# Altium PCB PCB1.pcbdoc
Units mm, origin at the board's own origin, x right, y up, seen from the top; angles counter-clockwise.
Board outline 92.1 x 134 mm, 2 copper layers (Top Layer, Bottom Layer); 90 components, 71 nets, 345 pads, 182 vias.
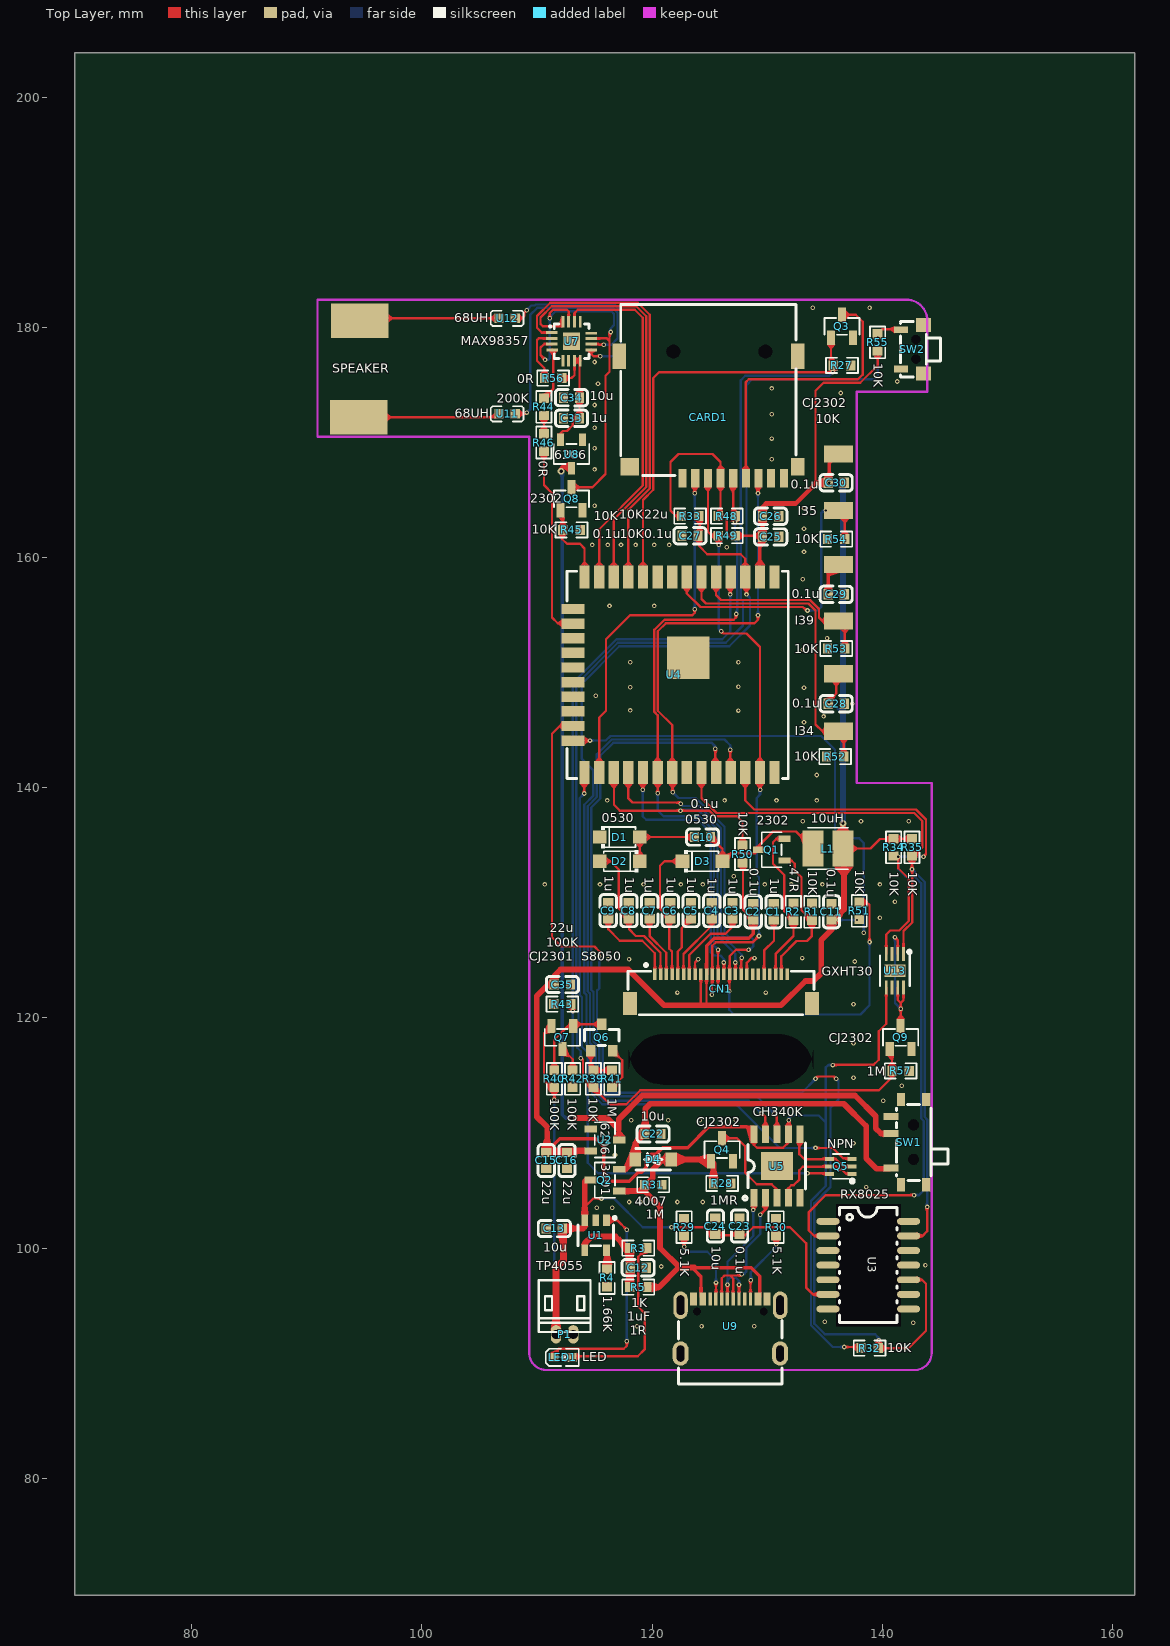
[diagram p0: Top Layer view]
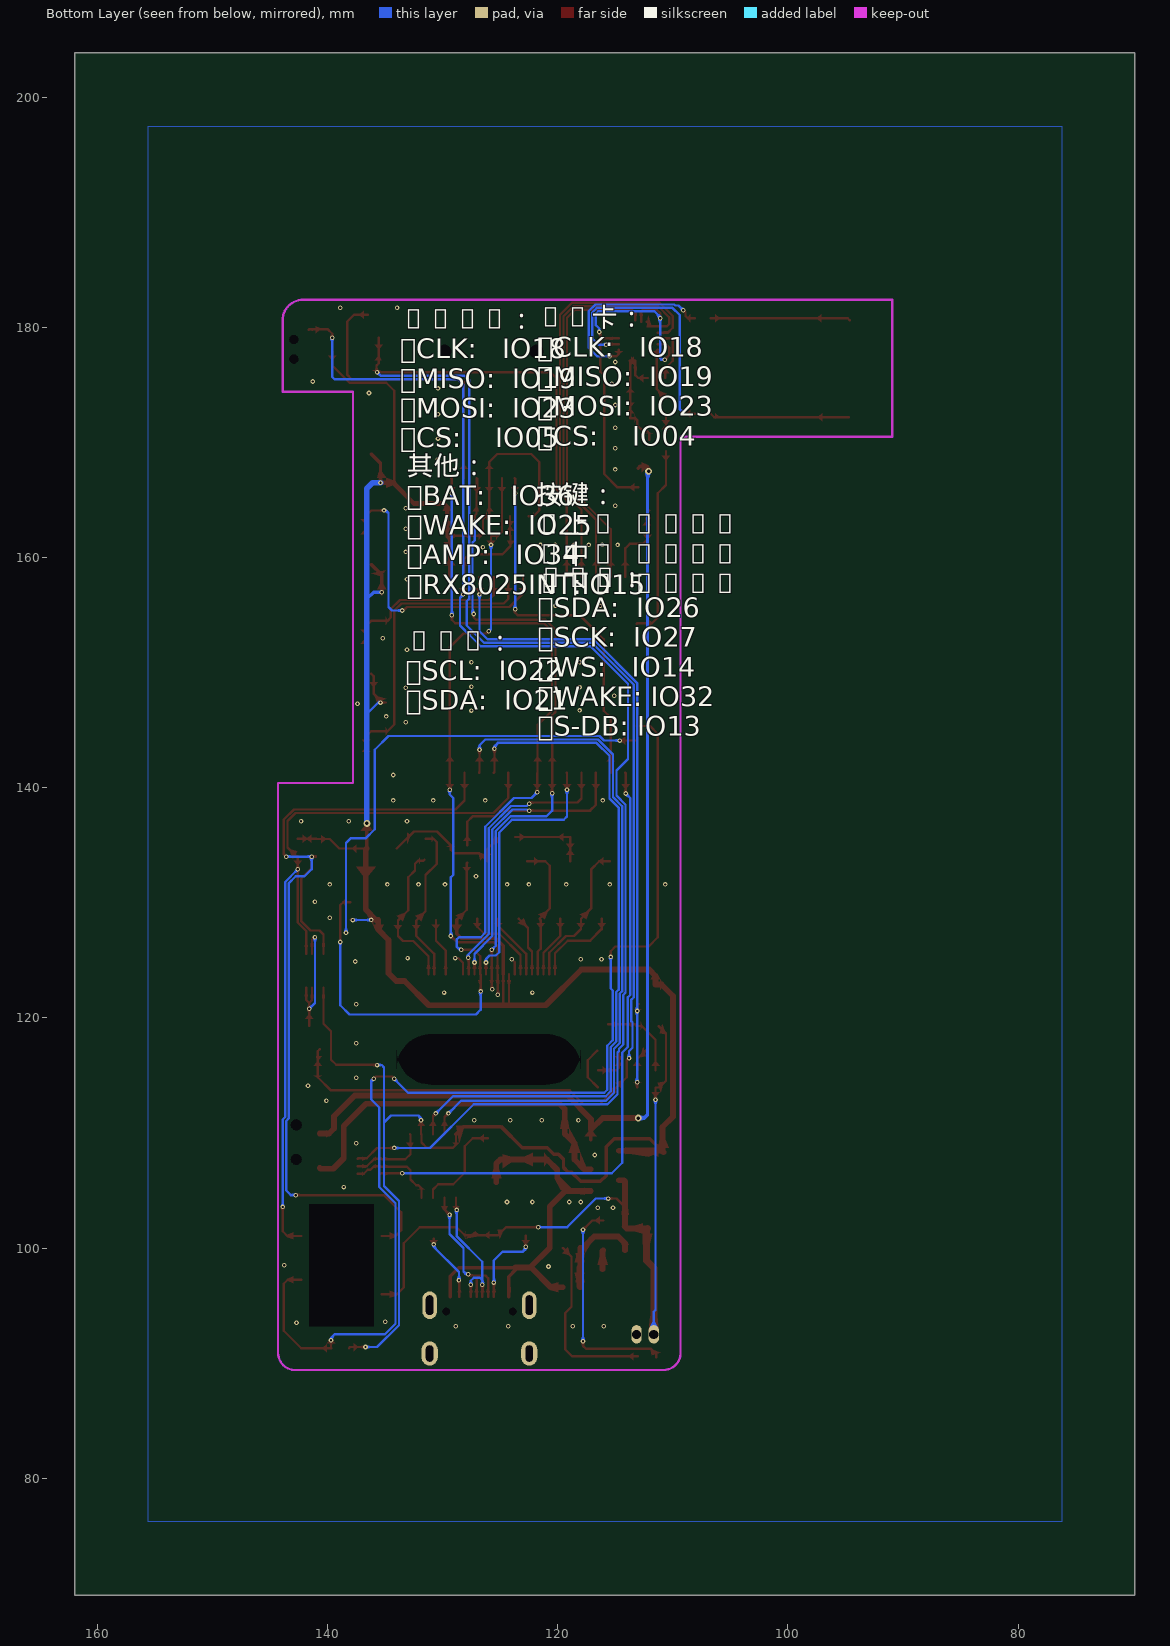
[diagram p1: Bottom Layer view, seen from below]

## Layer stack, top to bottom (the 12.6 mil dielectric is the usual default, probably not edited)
Top Layer: signal copper (thickness not stored)
Dielectric: dielectric 0.32, FR-4, Dk 4.8
Bottom Layer: signal copper (thickness not stored)

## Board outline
161.95,69.85 69.85,69.85 69.85,203.85 161.95,203.85
cut-out: 120.986,118.6 130.986,118.6 cw(c130.986,115.6) 133.986,115.6 133.986,117.2 cw(c130.986,117.2) 130.986,114.2 120.986,114.2 cw(c120.986,117.2) 117.986,117.2 117.986,115.6 cw(c120.986,115.6)
cut-out: 136,103.8 141.6,103.8 141.6,93.2 136,93.2

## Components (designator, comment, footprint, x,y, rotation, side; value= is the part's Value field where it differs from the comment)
C1 "CAP_0603" C0603 130.586,129.214 r270 top
C2 "CAP_0603" C0603 128.786,129.214 r270 top
C3 "CAP_0603" C0603 126.986,129.314 r270 top
C4 "CAP_0603" C0603 125.186,129.314 r270 top
C5 "CAP_0603" C0603 123.386,129.314 r270 top
C6 "CAP_0603" C0603 121.586,129.314 r270 top
C7 "CAP_0603" C0603 119.786,129.314 r270 top
C8 "CAP_0603" C0603 117.986,129.314 r270 top
C9 "CAP_0603" C0603 116.186,129.314 r270 top
C10 "CAP_0603" C0603 124.386,135.714 r180 top
C11 "CAP_0603" C0603 135.586,129.214 r270 top
C12 "CAP_0603" C0603 118.8,98.3 r0 top
C13 "CAP_0603" C0603 111.5,101.7 r180 top
C15 "CAP_0603" C0603 110.805,107.616 r90 top
C16 "CAP_0603" C0603 112.605,107.616 r90 top
C22 "CAP_0603" C0603 120.086,109.914 r180 top
C23 "CAP_0603" C0603 127.6,101.9 r270 top
C24 "CAP_0603" C0603 125.5,101.9 r270 top
C25 "CAP_0603" C0603 130.3,161.8 r180 top
C26 "CAP_0603" C0603 130.3,163.6 r180 top
C27 "CAP_0603" C0603 123.3,161.9 r0 top
C28 "CAP_0603" C0603 136,147.3 r0 top
C29 "CAP_0603" C0603 136,156.8 r0 top
C30 "CAP_0603" C0603 136,166.5 r0 top
C33 "CAP_0603" C0603 113,172.1 r0 top
C34 "CAP_0603" C0603 113,173.9 r0 top
C35 "CAP_0603" C0603 112.2,122.9 r180 top
CARD1 "XKTF-015-G" TF-SMD_XKTF-015-N 124.9,172.2 r180 top
CN1 "HW05150-240R00" FPC-SMD_24P-P0.50_HW05150-240R00 125.986,122.514 r0 top
D1 "MBR0530" SOD-123FL_L2.7-W1.8-LS3.7-RD 117.186,135.714 r0 top
D2 "MBR0530" SOD-123FL_L2.7-W1.8-LS3.7-RD 117.186,133.614 r180 top
D3 "MBR0530" SOD-123FL_L2.7-W1.8-LS3.7-RD 124.386,133.614 r0 top
D4 "SM4007PL_C64898" SOD-123F_L2.8-W1.8-LS3.7-RD 120.1,107.7 r0 top
L1 "SCCD32-100KT" IND-SMD_L3.5-W3.0 135.286,134.714 r0 top
LED1 "LED_0603-B" LED_0603 112.3,90.5 r0 top
P1 "弯针1.25*2" CON1.5*2-90 112.4,92.5 r180 top
Q1 "SL2302" SOT-23-3_L3.0-W1.7-P0.95-LS2.9-BR 130.386,134.614 r0 top
Q2 "CJ3401" SOT-23-3_L2.9-W1.6-P1.90-LS2.8-BR 115.9,105.9 r0 top
Q3 "CJ2302" SOT-23-3_L2.9-W1.3-P1.90-LS2.4-BR 136.5,180.1 r270 top
Q4 "CJ2302" SOT-23-3_L2.9-W1.3-P1.90-LS2.4-BR 126.085,108.547 r270 top
Q5 "PUMH9,115" SOT-363_L2.0-W1.3-P0.65-LS2.1-BL 136.4,107.1 r90 top
Q6 "S8050_SOT_NPN" S8050_SOT-23 115.5,118.3 r270 top
Q7 "CJ2301" SOT-23-3_L2.9-W1.3-P1.90-LS2.4-BR 112.2,118.3 r90 top
Q8 "CJ2302" SOT-23-3_L2.9-W1.3-P1.90-LS2.4-BR 113,165.1 r270 top
Q9 "CJ2302" SOT-23-3_L2.9-W1.3-P1.90-LS2.4-BR 141.6,118.3 r270 top
R1 "Res_0603" R0603 133.886,129.214 r270 top
R2 "Res_0603" R0603 132.286,129.214 r270 top
R3 "Res_0603" R0603 118.8,100 r0 top
R4 "Res_0603" R0603 116.1,97.4 r270 top
R5 "Res_0603" R0603 118.8,96.6 r180 top
R27 "Res_0603" R0603 136.5,176.7 r0 top
R28 "Res_0603" R0603 126.086,105.614 r180 top
R29 "Res_0603" R0603 122.786,101.814 r270 top
R30 "Res_0603" R0603 130.786,101.814 r90 top
R31 "Res_0603" R0603 120.1,105.5 r180 top
R32 "Res_0603" R0603 138.9,91.3 r180 top
R33 "Res_0603" R0603 123.3,163.6 r0 top
R34 "Res_0603" R0603 140.986,134.814 r270 top
R35 "Res_0603" R0603 142.586,134.814 r270 top
R39 "Res_0603" R0603 114.9,114.7 r90 top
R40 "Res_0603" R0603 111.5,114.7 r90 top
R41 "Res_0603" R0603 116.5,114.7 r270 top
R42 "Res_0603" R0603 113.1,114.7 r270 top
R43 "Res_0603" R0603 112.2,121.2 r180 top
R44 "Res_0603" R0603 110.6,173.1 r90 top
R45 "Res_0603" R0603 113,162.4 r180 top
R46 "Res_0603" R0603 110.6,170 r270 top
R48 "Res_0603" R0603 126.5,163.6 r0 top
R49 "Res_0603" R0603 126.5,161.9 r180 top
R50 "Res_0603" R0603 127.859,134.24 r90 top
R51 "Res_0603" R0603 138,129.3 r90 top
R52 "Res_0603" R0603 135.9,142.7 r180 top
R53 "Res_0603" R0603 136,152.1 r180 top
R54 "Res_0603" R0603 136,161.6 r180 top
R55 "Res_0603" R0603 139.6,178.7 r90 top
R56 "Res_0603" R0603 111.4,175.6 r180 top
R57 "Res_0603" R0603 141.6,115.4 r0 top
SW1 "MSK12CO2-BDM" SW-SMD_MSK12CO2-BDM 142.3,109.2 r90 top
SW2 "TS-1010-C-A" KEY-SMD_TX-1010-X-X 142.6,178.1 r270 top
U1 "TP4055" SOT-23-5_L3.0-W1.7-P0.95-LS2.8-BR 115.1,101.1 r90 top
U2 "ME6206A33M3G" SOT-23-3_L2.9-W1.6-P1.90-LS2.8-BR 115.9,109.4 r180 top
U3 "RX8025T-UB" SOIC-14_L10.1-W5.0-P1.27-LS7.4-BL 138.786,98.514 r270 top
U4 "ESP32-WROOM-32UE-N4_C2934568" WIFI-SMD_ESP32-WROOM-32UE-A 121.886,149.814 r270 top
U5 "CH340K" ESOP-10_L4.9-W3.9-P1.00-LS6.2-BL-EP 130.843,107.131 r0 top
U7 "MAX98357AETE+T" TQFN-16_L3.0-W3.0-P0.50-BL-EP1.5 113,178.8 r270 top
U8 "ME6206A33M3G" SOT-23-3_L2.9-W1.6-P1.90-LS2.8-BR 113,169 r90 top
U9 "TYPE-C16PIN母座 板上四脚三次molding" USB-SMD_TYPE-C16PIN 126.8,93.2 r0 top
U11 "EBLS1608-3R9K" L0603 107.4,172.5 r180 top
U12 "EBLS1608-3R9K" L0603 107.4,180.8 r180 top
U13 "GXHT30" DFN-8_L2.5-W2.5-P0.50-BL-EP 141.1,124.1 r180 top

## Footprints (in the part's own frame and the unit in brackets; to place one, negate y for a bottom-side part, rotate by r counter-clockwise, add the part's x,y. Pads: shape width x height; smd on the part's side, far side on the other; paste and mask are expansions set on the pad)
C0603 [mm]
  rect 0.8x0.9 smd paste+0 mask+0.051: 1(-0.7,0) 2(0.7,0)
  silkscreen extent -1.41,-0.71 1.39,0.72
CON1.5*2-90 [mm]
  oval 0.9x1.6 hole 0.8 paste+0 mask+0.102: 1(-0.75,0) 2(0.75,0)
  silkscreen extent -2.25,-4.7 2.25,-0.2
DFN-8_L2.5-W2.5-P0.50-BL-EP [mm]
  rect 0.25x1.25 smd paste+0 mask+0.051: 1(-0.75,-1.454) 2(-0.25,-1.454) 3(0.25,-1.454) 4(0.75,-1.454) 5(0.75,1.454) 6(0.25,1.454) 7(-0.25,1.454) 8(-0.75,1.454)
  rect 1.8x1.1 smd paste+0 mask+0.051: 9(0,0)
  silkscreen extent -1.39,-1.77 1.3,1.3
ESOP-10_L4.9-W3.9-P1.00-LS6.2-BL-EP [mm]
  rect 0.6x1.5 smd paste+0 mask+0.051: 1(-2,-2.75) 2(-1,-2.75) 3(0,-2.75) 4(1,-2.75) 5(2,-2.75) 6(2,2.75) 7(1,2.75) 8(0,2.75) 9(-1,2.75) 10(-2,2.75)
  rect 2.8x2.4 smd paste+0 mask+0.051: 11(0,0)
  silkscreen extent -2.94,-2.96 2.5,2
FPC-SMD_24P-P0.50_HW05150-240R00 [mm]
  rect 0.3x1 smd paste+0 mask+0.05: 1(-5.75,1.275) 2(-5.25,1.275) 3(-4.75,1.275) 4(-4.25,1.275) 5(-3.75,1.275) 6(-3.25,1.275) 7(-2.75,1.275) 8(-2.25,1.275) 9(-1.75,1.275) 10(-1.25,1.275) 11(-0.75,1.275) 12(-0.25,1.275) 13(0.25,1.275) 14(0.75,1.275) 15(1.25,1.275) 16(1.75,1.275) 17(2.25,1.275) 18(2.752,1.275) 19(3.25,1.275) 20(3.75,1.275) 21(4.25,1.275) 22(4.75,1.275) 23(5.25,1.275) 24(5.75,1.275)
  rect 1.2x2 smd paste+0 mask+0.05: 25(7.9,-1.275) 26(-7.9,-1.275)
  silkscreen extent -8.09,-2.24 8.07,2.21
IND-SMD_L3.5-W3.0 [mm]
  rect 1.8x3.12 smd paste+0 mask+0.051: 1(1.303,0) 2(-1.303,0)
  silkscreen extent -1.75,-1.8 1.75,1.8
KEY-SMD_TX-1010-X-X [mm]
  rect 0.6x1.2 smd paste+0 mask+0.051: 1(-1.7,-0.975) 2(1.7,-0.975)
  rect 1.2x1.3 smd paste+0 mask+0.051: 3(-2.1,0.975) 4(2.1,0.975)
  Multi-Layer board cut-out: -0.85,0.725 -1.023,0.685 -1.163,0.574 -1.24,0.414 -1.24,0.236 -1.163,0.076 -1.023,-0.035 -0.85,-0.075 -0.85,-0.075 -0.676,-0.035 -0.537,0.076 -0.46,0.236 -0.46,0.414 -0.537,0.574 -0.676,0.685 -0.85,0.725
  Multi-Layer board cut-out: 0.85,0.725 0.677,0.685 0.537,0.574 0.46,0.414 0.46,0.236 0.537,0.076 0.677,-0.035 0.85,-0.075 0.85,-0.075 1.024,-0.035 1.163,0.076 1.24,0.236 1.24,0.414 1.163,0.574 1.024,0.685 0.85,0.725
  silkscreen extent -2.4,-1.03 2.4,2.48
L0603 [mm]
  rect 0.8x0.864 smd paste-100 mask+0.051: 1(-0.7,0) 2(0.7,0)
  silkscreen extent -1.42,-0.65 1.41,0.67
LED_0603 [mil]
  rect 31.5x31.5 smd paste+0 mask+2: 1(-33.5,-0.4) 2(29.5,-0.2)
  silkscreen extent -61,-30 53,30
R0603 [mm]
  rect 0.806x0.864 smd paste-100 mask+0.051: 1(-0.753,0) 2(0.753,0)
  silkscreen extent -1.39,-0.66 1.39,0.66
S8050_SOT-23 [mm]
  rect 1x0.8 smd paste+0 mask+0.051: 1(1.15,-0.823) 2(1.15,1.077) 3(-1.15,0.127)
  silkscreen extent -0.7,-1.37 0.7,1.63
SOD-123F_L2.8-W1.8-LS3.7-RD [mm]
  rect 1x1.2 smd paste+0 mask+0.051: 1(-1.55,0) 2(1.55,0)
  silkscreen extent -1.52,-0.93 1.49,0.95
SOD-123FL_L2.7-W1.8-LS3.7-RD [mm]
  rect 1.2x1.15 smd paste+0 mask+0.051: 1(-1.735,0) 2(1.735,0)
  silkscreen extent -1.6,-0.95 1.38,0.95
SOIC-14_L10.1-W5.0-P1.27-LS7.4-BL [mm]
  oval 0.6x2 smd paste+0 mask+0.051: 1(-3.81,-3.5) 2(-2.54,-3.5) 3(-1.27,-3.5) 4(0,-3.5) 5(1.27,-3.5) 6(2.54,-3.5) 7(3.81,-3.5) 8(3.81,3.5) 9(2.54,3.5) 10(1.27,3.5) 11(0,3.5) 12(-1.27,3.5) 13(-2.54,3.5) 14(-3.81,3.5)
  silkscreen extent -5,-2.5 5,2.5
SOT-23-3_L2.9-W1.3-P1.90-LS2.4-BR [mm]
  rect 1.25x0.7 smd paste+0 mask+0.051: 1(1,-0.95) 2(1,0.95) 3(-1,0)
  silkscreen extent -0.73,-1.53 0.73,1.53
SOT-23-3_L2.9-W1.6-P1.90-LS2.8-BR [mm]
  rect 1.07x0.6 smd paste+0 mask+0.051: 1(1.235,-0.95) 2(1.235,0.95) 3(-1.235,0)
  silkscreen extent -0.88,-1.54 0.88,1.54
SOT-23-3_L3.0-W1.7-P0.95-LS2.9-BR [mm]
  rect 1.037x0.532 smd paste+0 mask+0.051: 1(1.101,-0.95) 2(1.101,0.95) 3(-1.101,0)
  silkscreen extent -0.86,-1.53 0.86,1.53
SOT-23-5_L3.0-W1.7-P0.95-LS2.8-BR [mm]
  rect 1x0.6 smd paste+0 mask+0.051: 1(1.3,-0.95) 2(1.3,0) 3(1.3,0.95) 4(-1.3,0.95) 5(-1.3,-0.95)
  silkscreen extent -0.9,-1.78 1.65,1.55
SOT-363_L2.0-W1.3-P0.65-LS2.1-BL [mm]
  rect 0.35x0.78 smd paste+0 mask+0.051: 1(-0.65,-0.99) 2(0,-0.99) 3(0.65,-0.99) 4(0.65,0.99) 5(0,0.99) 6(-0.65,0.99)
  silkscreen extent -1.43,-1.14 1.08,0.7
SW-SMD_MSK12CO2-BDM [mm]
  rect 0.6x1.3 smd paste+0 mask+0.051: 1(2.25,1.525) 2(0.75,1.525) 3(-2.25,1.525)
  rect 1.15x0.7 smd paste+0 mask+0.051: 4(-3.7,-1.525) 4(-3.7,0.675) 4(3.7,-1.525) 4(3.7,0.675)
  Multi-Layer board cut-out: -1.5,-0.9 -1.294,-0.853 -1.129,-0.721 -1.037,-0.531 -1.037,-0.319 -1.129,-0.129 -1.294,0.003 -1.5,0.05 -1.5,0.05 -1.706,0.003 -1.871,-0.129 -1.963,-0.319 -1.963,-0.531 -1.871,-0.721 -1.706,-0.853 -1.5,-0.9
  Multi-Layer board cut-out: 1.5,-0.9 1.706,-0.853 1.871,-0.721 1.963,-0.531 1.963,-0.319 1.871,-0.129 1.706,0.003 1.5,0.05 1.5,0.05 1.294,0.003 1.129,-0.129 1.037,-0.319 1.037,-0.531 1.129,-0.721 1.294,-0.853 1.5,-0.9
  silkscreen extent -3.33,-3.42 3.27,1.08
TF-SMD_XKTF-015-N [mm]
  rect 0.7x1.6 smd paste+0 mask+0.051: 1(2.25,5.3) 2(1.15,5.3) 3(0.05,5.3) 4(-1.05,5.3) 5(-2.15,5.3) 6(-3.25,5.3) 7(-4.35,5.3) 8(-5.45,5.3) 9(-6.55,5.3)
  rect 1.2x1.5 smd paste+0 mask+0.051: 10(-7.75,4.3)
  rect 1.2x2.2 smd paste+0 mask+0.051: 11(-7.75,-5.3) 13(7.75,-5.3)
  rect 1.6x1.5 smd paste+0 mask+0.051: 12(6.85,4.3)
  Multi-Layer board cut-out: 2.45,-5.7 2.509,-5.96 2.676,-6.169 2.917,-6.285 3.184,-6.285 3.424,-6.169 3.591,-5.96 3.65,-5.7 3.65,-5.7 3.591,-5.44 3.424,-5.231 3.184,-5.115 2.917,-5.115 2.676,-5.231 2.509,-5.44 2.45,-5.7
  Multi-Layer board cut-out: -5.55,-5.7 -5.491,-5.96 -5.324,-6.169 -5.083,-6.285 -4.816,-6.285 -4.576,-6.169 -4.409,-5.96 -4.35,-5.7 -4.35,-5.7 -4.409,-5.44 -4.576,-5.231 -4.816,-5.115 -5.083,-5.115 -5.324,-5.231 -5.491,-5.44 -5.55,-5.7
  silkscreen extent -7.62,-9.78 7.62,5.08
TQFN-16_L3.0-W3.0-P0.50-BL-EP1.5 [mm]
  rect 0.25x1 smd mask+0.051: 1(-0.75,-1.7) 2(-0.249,-1.7) 3(0.252,-1.7) 4(0.752,-1.683) 9(0.75,1.7) 10(0.25,1.7) 11(-0.25,1.7) 12(-0.7,1.7)
  rect 1x0.25 smd mask+0.051: 5(1.716,-0.748) 6(1.7,-0.248) 7(1.7,0.252) 8(1.7,0.752) 13(-1.7,0.752) 14(-1.7,0.252) 15(-1.7,-0.248) 16(-1.7,-0.748)
  rect 1.5x1.5 smd paste-100 mask+0.051: 17(0,0)
  silkscreen extent -1.5,-1.9 1.5,1.5
USB-SMD_TYPE-C16PIN [mm]
  oval 1.25x2.4 hole 0.65 slot 1.7 at 90 deg paste+0 mask+0.05: 17(-4.325,1.835) 18(4.325,1.835)
  oval 1.4x2.1 hole 0.65 slot 1.4 at 90 deg paste+0 mask+0.05: 19(-4.325,-2.365) 20(4.325,-2.365)
  rect 0.3x1.15 smd paste-100 mask+0.05: A1(-3.35,2.365) A4(-2.55,2.365) A5(-1.25,2.365) A6(-0.25,2.365) A7(0.25,2.365) A8(1.25,2.365) A9(2.55,2.365) A12(3.35,2.365) B1(3.05,2.365) B4(2.25,2.365) B5(1.75,2.365) B6(0.75,2.365) B7(-0.75,2.365) B8(-1.75,2.365) B9(-2.25,2.365) B12(-3.05,2.365)
  Multi-Layer board cut-out: -2.575,1.285 -2.607,1.426 -2.697,1.539 -2.828,1.602 -2.972,1.602 -3.103,1.539 -3.193,1.426 -3.225,1.285 -3.225,1.285 -3.193,1.144 -3.103,1.031 -2.972,0.968 -2.828,0.968 -2.697,1.031 -2.607,1.144 -2.575,1.285
  Multi-Layer board cut-out: 3.225,1.285 3.193,1.426 3.103,1.539 2.972,1.602 2.828,1.602 2.697,1.539 2.607,1.426 2.575,1.285 2.575,1.285 2.607,1.144 2.697,1.031 2.828,0.968 2.972,0.968 3.103,1.031 3.193,1.144 3.225,1.285
  silkscreen extent -4.5,-5.01 4.5,0.52
WIFI-SMD_ESP32-WROOM-32UE-A [mm]
  rect 2x0.9 smd paste+0 mask+0.051: 1(-8.5,8.755) 2(-8.5,7.485) 3(-8.5,6.215) 4(-8.5,4.945) 5(-8.5,3.675) 6(-8.5,2.405) 7(-8.5,1.135) 8(-8.5,-0.135) 9(-8.5,-1.405) 10(-8.5,-2.675) 11(-8.5,-3.945) 12(-8.5,-5.215) 13(-8.5,-6.485) 14(-8.5,-7.755) 25(8.5,-7.755) 26(8.5,-6.485) 27(8.5,-5.215) 28(8.5,-3.945) 29(8.5,-2.675) 30(8.5,-1.405) 31(8.5,-0.135) 32(8.5,1.135) 33(8.5,2.405) 34(8.5,3.675) 35(8.5,4.945) 36(8.5,6.215) 37(8.5,7.485) 38(8.5,8.755)
  rect 0.9x2 smd paste+0 mask+0.051: 15(-5.715,-8.755) 16(-4.445,-8.755) 17(-3.175,-8.755) 18(-1.905,-8.755) 19(-0.635,-8.755) 20(0.635,-8.755) 21(1.905,-8.755) 22(3.175,-8.755) 23(4.445,-8.755) 24(5.715,-8.755)
  rect 3.7x3.7 smd paste+0 mask+0.051: 39(-1.5,1.255)
  silkscreen extent -9,-9.27 9.02,9.95

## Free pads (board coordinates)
  rect 5x3 smd mask+0.051: 1(94.5,172.2) 1(94.6,180.6)
  rect 2.5x1.5 smd mask+0.051: 1(136.2,144.9) 1(136.2,149.9) 1(136.2,154.5) 1(136.2,159.4) 1(136.2,164.1) 1(136.2,169)

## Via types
v1: diameter 0.4, hole 0.2, Top Layer to Bottom Layer, 179 vias
v2: diameter 0.6, hole 0.3, Top Layer to Bottom Layer, 3 vias

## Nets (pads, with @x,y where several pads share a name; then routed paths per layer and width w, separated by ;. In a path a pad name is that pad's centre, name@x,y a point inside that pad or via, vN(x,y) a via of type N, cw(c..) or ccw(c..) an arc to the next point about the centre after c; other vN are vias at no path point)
3V3: C2.2 C11.2 C15.2 C16.2 C25.2 C26.2 C28.1 C29.1 C30.1 C35.2 CARD1.4 CN1.9 CN1.10 L1.1 pad.1@136.2,149.9 pad.1@136.2,159.4 pad.1@136.2,169 R32.2 R33.1 R34.1 R35.1 R48.1 R49.1 R50.1 R51.1 R55.1 U2.2 U4.2 U5.7 U5.10 U13.5 | length 252.9
  Top Layer w0.2: R33.1 122.1,163.6 121.6,164.1 121.6,168.3 122.3,169 125.25,169 125.95,168.3 CARD1.4 125.95,163.803 R48.1 126.264,163.6 126.5,163.364 126.5,162.1 126.7,161.9 R49.1 129.5,161.9 C25.2 ; 124.206,121.1 124.235,121.129 CN1.9 ; 124.685,121.1 124.736,121.151 CN1.10 ; R50.1 127.9,133.445 127.9,129.4 C2.2 ; U5.10 128.843,108.98 129.109,108.714 131.386,108.714 131.843,109.172 U5.7 131.886,109.923 v1(131.886,111.114) ; 134.2,166.5 134.2,174.498 134.9,175.198 138.098,175.198 139.6,176.7 R55.1 ; C28.1@134.939,147.4 v1(135.4,147.4) 135.4,147.6 136,148.2 136,149.7 pad.1@136.2,149.9 ; C29.1 v1(135.3,157) ; v1(135.7,115.9) 135.72,115.92 139.25,115.92 139.7,116.37 139.7,118.846 140.35,119.496 U13.5 ; C11.2@135.786,128.514 v1(136.2,128.514) ; L1.1 138.986,134.714 139.812,135.541 140.958,135.541 R34.1 R35.1 ; v1(136.7,91.4) 138.047,91.4 R32.2 ; v1(137.8,128.5) 137.953,128.5 R51.1
  Top Layer w0.3: C15.2@110.94,108.45 111.99,109.5 115.1,109.5 115.8,108.8 115.8,106.3 116.3,105.8 118,105.8 118.8,106.6 119.1,106.6 119.5,107 119.5,107.7 119.936,108.136 120.336,108.136 120.927,108.727 123.1,108.727 124.933,110.56 128.164,110.56 U5.10 ; CN1.10 124.736,126.264 125.386,126.914 128.386,126.914 128.786,127.314 C2.2 ; U4.2 129.371,161.571 C25.2 C26.2 ; v1(135.3,157) 135.3,158.5 pad.1@136.2,159.4 ; v1(135.4,166.5) 135.4,168.2 pad.1@136.2,169 ; L1.1 v2(136.589,136.9)
  Top Layer w0.4: C26.2 129.6,164.4 129.9,164.7 132.5,164.7 134.2,166.4 134.2,166.5 v1(135.4,166.5)
  Top Layer w0.5: C15.2 110.94,108.45 U2.2 ; C15.2@110.886,108.396 110.886,110.514 109.986,111.414 109.986,121.914 110.971,122.9 C35.2 111.5,123.651 112.049,124.2 117.936,124.2 121.036,121.1 124.206,121.1 124.685,121.1 131.208,121.1 133.323,123.214 134.03,123.214 134.695,123.88 134.695,126.768 135.586,127.659 C11.2 135.786,128.514 136.686,129.414 136.686,134.617 L1.1
  Bottom Layer w0.2: v1(131.886,111.114) 131.886,111.314 132.086,111.514 134.486,111.514 135.1,110.9 ; v1(135.4,147.4) 135.606,147.4 136.589,146.417 ; v1(135.7,115.9) 135.3,115.9 135.1,115.7 135.1,110.9 ; v1(136.2,128.514) 136.214,128.5 v1(137.8,128.5) ; v1(136.7,91.4) 135.7,91.4 133.8,93.3 133.8,104.1 135.1,105.4 135.1,110.9
  Bottom Layer w0.3: v1(135.3,157) 136,157 136.589,156.411
  Bottom Layer w0.5: v1(135.4,166.5) 136.1,166.5 136.589,166.011 136.589,156.411 136.589,146.417 v2(136.589,136.9)
8025INT: R32.1 U3.10 U4.23 | length 97.6
  Top Layer w0.2: U4.23 111.98,145.369 111.3,144.69 111.3,127 112.1,126.2 115,126.2 115.4,125.8 v1(115.4,125.3) ; v1(134.2,114.7) 134.4,114.9 135.8,114.9 v1(136,114.7) ; v1(139.7,92) 139.7,91.347 R32.1 142.286,91.3 143.8,92.814 143.8,96.9 143.456,97.244 U3.10
  Bottom Layer w0.2: v1(115.4,125.3) 115.4,122.561 115.21,122.371 115.21,118.071 115.706,117.575 115.706,113.748 115.952,113.502 133.002,113.502 v1(134.2,114.7) ; 134.102,103.9 134.102,93.425 135.014,92.514 139.386,92.514 139.7,92.2 v1(139.7,92) ; 134.102,103.902 135.5,105.3 135.5,112.207 136.2,112.907 136.2,114.5 v1(136,114.7)
$1N246: C1.2 CN1.20 | length 5.1
  Top Layer w0.2: CN1.20 129.736,125.864 130.586,126.714 C1.2
$1N372: C3.2 CN1.7 | length 7.1
  Top Layer w0.2: CN1.7 123.235,125.464 125.083,127.312 126.386,127.312 126.986,127.912 C3.2
$1N423: C4.2 CN1.6 | length 5.8
  Top Layer w0.2: CN1.6 122.736,125.564 125.186,128.014 C4.2
$1N427: C5.2 CN1.5 | length 5.3
  Top Layer w0.2: CN1.5 122.235,125.764 122.586,126.114 122.586,127.814 C5.2
$1N505: C7.2 CN1.3 | length 5.4
  Top Layer w0.2: C7.2 119.786,127.114 121.235,125.665 CN1.3
$1N562: C9.2 CN1.1 | length 7.6
  Top Layer w0.2: C9.2 116.186,127.714 117.186,126.714 119.135,126.714 120.235,125.614 CN1.1
$1N900: C10.2 D1.2 D2.1 | length 6.9
  Top Layer w0.2: D2.1 D1.2 C10.2
$1N1154: C10.1 D3.2 L1.2 Q1.3 | length 12.3
  Top Layer w0.2: C10.1 126.121,134.679 D3.2 126.806,134.3 128.97,134.3 Q1.3 129.284,134.984 130.5,136.2 132.497,136.2 L1.2
$1N1499: LED1.1 U1.1 | length 19.1
  Top Layer w0.2: LED1.1 111.449,90.79 111.9,91.241 117.541,91.241 117.8,91.5 v1(117.8,91.9) ; U1.1 117,102.4 v1(117.8,101.6)
  Bottom Layer w0.2: v1(117.8,91.9) v1(117.8,101.6)
$1N1521: LED1.2 R3.2 | length 15.9
  Top Layer w0.2: LED1.2@113.049,90.595 118.749,90.595 119.349,91.195 119.349,94.351 118.8,94.9 118.8,99.247 R3.2
$1N1592: R4.1 U1.5 | length 1.7
  Top Layer w0.5: U1.5 116.1,99.75 R4.1
$1N2827: CARD1.6 Q3.3 | length 25.4
  Top Layer w0.2: CARD1.6 128.15,175.25 128.4,175.5 137.9,175.5 138.3,175.9 138.3,180.5 137.7,181.1 Q3.3
$1N3650: Q4.3 U5.3 | length 8.7
  Top Layer w0.2: Q4.3 127.386,109.547 128.085,108.848 128.085,106.547 129.085,105.547 130.385,105.547 130.843,105.088 U5.3
$1N5042: R29.2 U9.A5 | length 7.5
  Top Layer w0.2: v1(122.786,100.114) R29.2 ; U9.A5@125.55,95.757 v1(125.55,97)
  Bottom Layer w0.2: v1(122.786,100.114) 122.786,99.914 123.029,99.671 124.802,99.671 125.55,98.922 v1(125.55,97)
  other v1: 125.55,97
$1N5135: R30.1 U9.B5 | length 6
  Top Layer w0.2: U9.B5@128.55,95.757 128.55,97.179 v1(128.586,97.214) ; v1(130.786,100.314) R30.1@130.786,100.812
  Bottom Layer w0.2: v1(128.586,97.214) 128.586,97.914 130.786,100.114 v1(130.786,100.314)
$1N9174: Q6.1 R39.2 R41.1 | length 3.4
  Top Layer w0.2: Q6.1 114.677,115.676 R39.2 R41.1
$1N9291: Q6.3 Q7.1 R40.2 | length 7.3
  Top Layer w0.2: R40.2 111.5,118.1 112.7,119.3 Q7.1 113.3,119.45 Q6.3
$1N9318: Q7.3 R42.1 | length 2.2
  Top Layer w0.2: Q7.3 113.1,116.4 R42.1
$2N220: R44.2 U7.4 | length 4.6
  Top Layer w0.2: R44.2 111.4,174.653 111.4,177.966 U7.4
$2N1483: R56.2 U7.2 | length 4.9
  Top Layer w0.2: R56.2 110.647,176.453 110,177.1 110,178.9 110.149,179.049 U7.2
$2N1555: U7.10 U11.1 | length 22.5
  Top Layer w0.2: U11.1 109,172.5 v1(109.1,172.6) ; U7.10 115.351,178.55 115.401,178.5 v1(115.8,178.5)
  Bottom Layer w0.2: v1(109.1,172.6) 109.4,172.9 109.4,181.08 110.02,181.7 116.6,181.7 116.998,181.302 116.998,179.048 116.45,178.5 v1(115.8,178.5)
$2N1588: U7.9 U12.1 | length 16.6
  Top Layer w0.2: U12.1 108.7,180.8 108.9,181 108.9,181.3 v1(109.1,181.5) ; U7.9 114.7,177.7 114.9,177.5 v1(115.5,177.5)
  Bottom Layer w0.2: v1(109.1,181.5) 109.5,181.9 109.793,181.9 109.895,182.002 116.725,182.002 117.3,181.427 117.3,178.223 116.577,177.5 v1(115.5,177.5)
$4N231: Q9.3 U13.2 U13.7 U13.8 | length 12.9
  Top Layer w0.2: v1(141.1,127) 141.35,126.75 U13.2 ; U13.7 141.35,121.55 141.6,121.3 ; Q9.3 v1(141.6,120.8) 141.6,121.3 ; U13.8 141.85,121.55 141.6,121.3
  Bottom Layer w0.2: v1(141.1,127) 141.1,121.3 v1(141.6,120.8)
  other v1: 141.1,127
ADC-BAT: R42.2 R43.1 U4.4 | length 56.1
  Top Layer w0.2: R43.1 113.1,121.053 v1(113.1,120.6) ; R42.2 v1(113.1,114.4) ; v1(126.8,156.8) 126.8,158.284 U4.4
  Bottom Layer w0.2: v1(113.1,114.4) v1(113.1,120.6) 113.1,149.1 116.9,152.9 126.1,152.9 126.8,153.6 v1(126.8,156.8)
BUSY: CN1.16 U4.28 | length 24.8
  Top Layer w0.2: U4.28 117.941,139.059 118.286,138.714 122.386,138.714 v1(122.486,138.614) ; CN1.16 127.736,125.164 v1(127.786,125.214)
  Bottom Layer w0.2: v1(122.486,138.614) 122.686,138.414 124.067,138.414 125.992,136.49 125.992,127.291 127.786,125.497 v1(127.786,125.214)
CLK: CARD1.5 CN1.12 R48.2 U4.30 | length 56.5
  Top Layer w0.2: v1(120.486,139.514) 120.486,141.309 U4.30 120.481,146.292 120.198,146.575 120.198,153.725 121.073,154.6 127.1,154.6 127.3,154.8 v1(127.3,155.1) ; v1(125.7,122.5) 125.736,122.536 CN1.12 v1(125.736,125.914) ; 127,165.7 127,166.85 CARD1.5 127.05,163.803 R48.2 127.2,163.547 v1(127.2,163.1)
  Bottom Layer w0.2: v1(120.486,139.514) 120.486,138.014 120.984,137.516 124.111,137.516 125.388,136.239 125.388,126.262 v1(125.736,125.914) ; v1(127.2,163.1) 127.2,161.5 127.398,161.302 127.398,155.198 v1(127.3,155.1)
CS: CN1.13 U4.29 | length 23.4
  Top Layer w0.2: v1(119.196,139.814) 119.196,141.3 U4.29 ; CN1.13 v1(126.235,124.814)
  Bottom Layer w0.2: v1(119.196,139.814) 119.196,137.504 119.486,137.214 123.986,137.214 125.086,136.114 125.086,125.714 125.386,125.414 125.935,125.414 126.235,125.114 v1(126.235,124.814)
CS-OUT: U4.24 | length 41.1
  Top Layer w0.2: U4.24 v1(114.6,144.099)
  Bottom Layer w0.2: v1(114.6,144.099) 115.972,144.099 116.375,144.502 134.698,144.502 135.9,143.3 135.9,136.4 136.7,135.6 138,135.6 138.4,135.2 v1(138.4,127.4)
DATA+: U5.1 U9.A6 U9.B6 | length 12.2
  Top Layer w0.2: U9.A6@126.55,95.757 v1(126.55,96.814) ; U9.B6@127.55,95.757 v1(127.55,96.814) ; v1(128.786,103.314) 128.843,103.372 U5.1
  Bottom Layer w0.2: v1(126.55,96.814) 126.55,97.179 ; v1(127.55,96.814) 127.55,97.15 127.286,97.414 126.786,97.414 126.55,97.179 ; v1(128.786,103.314) 128.786,101.042 126.55,98.806 126.55,97.179
DATA-: U5.2 U9.A7 U9.B7 | length 13.1
  Top Layer w0.2: U9.B7@126.05,95.757 126.05,97.379 126.286,97.614 126.786,97.614 ; U9.A7@127.05,95.757 127.05,97.35 126.786,97.614 ; v1(127.786,97.714) 127.686,97.614 126.786,97.614 ; v1(129.4,102.9) 129.843,103.343 U5.2
  Bottom Layer w0.2: v1(127.786,97.714) 127.958,97.714 128.186,97.942 128.186,100.014 129.4,101.229 v1(129.4,102.9)
DC: CARD1.7 CN1.14 R51.2 U4.31 | length 83.8
  Top Layer w0.2: v1(121.786,139.614) 121.786,141.279 U4.31 121.751,145.449 120.5,146.7 120.5,153.6 121.198,154.298 128.898,154.298 129.2,154.6 v1(129.2,155) ; v1(126.7,122.3) 126.7,123.754 CN1.14 126.736,125.364 127.286,125.914 v1(128.386,125.914) ; v1(129.2,165.6) 129.2,166.85 CARD1.7 ; R51.2 138.647,130.053 138.9,129.8 v1@138.9,126.5
  Bottom Layer w0.2: v1(121.786,139.614) 122.284,139.116 123.792,139.116 126.294,136.615 126.294,127.416 126.696,127.014 128.586,127.014 128.786,126.814 128.786,126.214 128.486,125.914 v1(128.386,125.914) ; v1(126.7,122.3) 126.7,120.7 127.098,120.302 132.6,120.302 132.602,120.3 138.1,120.3 138.9,121.1 v1(138.9,126.6) ; v1(129.2,155) v1(129.2,165.6)
DIN: CARD1.3 CN1.11 R49.2 U4.37 | length 52
  Top Layer w0.2: CARD1.3 124.85,162.25 125.2,161.9 R49.2 125.8,161.847 v1(125.8,161.1) ; v1(125.2,122) 125.2,123.754 CN1.11 125.235,126.266 125.531,126.562 128.734,126.562 v1(129.286,127.114) ; v1(126,153.6) 126.2,153.4 128.2,153.4 129.371,152.229 U4.37 129.371,139.829 v1(129.386,139.814)
  Bottom Layer w0.2: v1(125.8,161.1) 125.8,153.8 v1(126,153.6) ; v1(129.286,127.114) 129.286,132.214 129.088,132.412 129.088,139.116 129.386,139.414 v1(129.386,139.814)
DTR: Q5.1 Q5.5 U5.4 | length 7.9
  Top Layer w0.2: U5.4 131.843,105.205 132.099,105.461 132.299,105.461 132.799,105.961 132.799,106.761 133.099,107.061 135.371,107.061 Q5.5 135.973,107.1 136.275,106.798 136.501,106.798 136.849,106.45 Q5.1
EN: C27.2 Q5.3 R33.2 R55.2 SW2.1 U4.3 | length 127.3
  Top Layer w0.2: R33.2@124.153,163.6 124.153,161.953 124.1,161.9 124.1,161 124.8,160.3 127.7,160.3 128.101,159.899 U4.3 128.2,158.215 v1(128.2,156.8) ; v1(134.2,108.7) 135.7,108.7 136.6,107.8 137.34,107.8 Q5.3 ; v1(139.6,179.1) R55.2 140,179.853 SW2.1@141.272,179.853 ; SW2.1@141.325,179.8 SW2.1@141.272,179.853 ; SW2.1 141.572,179.853 SW2.1@141.272,179.853
  Bottom Layer w0.2: 128.698,175.498 128.2,175 v1(128.2,156.8) 128.5,156.5 128.5,154.1 126.696,152.296 117.15,152.296 113.9,149.046 113.9,142.5 114.898,141.502 114.898,139.319 114.104,138.525 114.104,122.196 114.304,121.996 114.304,117.696 114.675,117.325 114.675,117.125 114.8,117 114.8,113.373 115.675,112.498 127.302,112.498 131.1,108.7 v1(134.2,108.7) ; 128.7,175.498 139.398,175.498 139.6,175.7 v1(139.6,179.1)
GDR: CN1.23 Q1.1 R1.2 | length 12.8
  Top Layer w0.2: CN1.23 131.235,125.364 132.556,126.685 133.456,126.685 133.886,127.114 R1.2 132.986,129.361 132.986,132.214 132.4,132.8 132.4,133.4 132.136,133.664 131.662,133.664 Q1.1@131.575,133.752
GND: C1.1 C2.1 C3.1 C4.1 C5.1 C6.1 C7.1 C8.1 C9.1 C11.1 C12.2 C13.2 C15.1 C16.1 C22.1 C23.1 C24.1 C25.1 C26.1 C27.1 C28.2 C29.2 C30.2 C33.1 C34.1 C35.1 CN1.8 CN1.17 D1.1 P1.1 Q3.2 Q4.2 Q6.2 Q8.2 Q9.2 R1.1 R2.1 R4.2 R27.2 R28.1 R29.1 R30.2 R31.1 R41.2 R43.2 R45.1 R52.2 R53.2 R54.2 R57.2 SW2.2 U1.2 U2.1 U3.7 U3.11 U4.1 U4.15 U4.38 U4.39 U8.1 U9.17 U9.18 U9.19 U9.20 U9.A1 U9.A12 U9.B1 U9.B12 | length 7.2
  Top Layer w0.2: R41.2 117.4,114.847 117.4,116.327 Q6.2 ; CN1.8 123.736,124.836 v1(124,125.1) ; CN1.17 128.235,124.8 128.635,125.2 v1(128.9,125.2)
  other v1: 116,93.2 118.69,93.2 124.3,93.2 128.868,93.2 142.704,93.514 135,93.6 120.8,98.4 143.753,98.514 115.2,103.5 116.529,103.5 118,104 119,104 122.2,104 124.411,104 138.6,105.3 116.776,108.091 137.5,109.1 118.2,111.1 121.4,111.1 124.135,111.1 127.266,111.1 140.1,112.8 141.7,114.1 137.5,114.8 137.5,117.8 137.5,121.189 122.2,122.2 129.877,122.2 137.6,124.9 116.2,125.1 118,125.1 133.048,125.2 139.8,128.713 141.1,130.1 110.663,131.6 115.477,131.6 119.255,131.6 122.504,131.6 124.4,131.6 129.8,131.6 132.1,131.6 134.8,131.6 139.8,131.6 127.1,132.3 133.1,137.1 138.152,137.1 142.302,137.1 130.813,138.899 116.1,138.9 126.3,138.9 134.3,138.9 134.3,141.112 133.2,145.7 134.9,146.2 118.1,146.719 127.5,146.705 137.4,147.3 115.1,148 133.2,148.7 118.1,148.744 127.5,148.775 118.1,150.9 127.5,150.9 133.1,152 135.205,152.994 116.3,155.8 120.2,155.8 133.1,158.112 133.2,160.494 126.5,160.9 114.8,161.1 116.138,161.1 117.3,161.1 118.565,161.1 120.2,161.1 121.498,161.1 133.2,162.5 133.2,164.3 115,164.5 115,167.66 130.4,168.552 115,169.5 130.4,170.343 115,171.281 130.4,172.457 115,173.258 136.4,174.3 130.4,174.7 115.3,175.1 141.3,175.3 115,177 133.959,181.7 138.9,181.7
I2S-SCK: U4.12 U7.16 | length 36.6
  Top Layer w0.2: U7.16 111.852,180.1 110.502,180.1 110.302,180.3 110.302,180.875 111.273,181.846 118.627,181.846 119.498,180.975 119.498,166.138 116.671,163.31 U4.12
I2S-SDA: U4.11 U7.1 | length 36.8
  Top Layer w0.2: U7.1 110.415,179.55 110,179.965 110,181 111.148,182.148 118.752,182.148 119.8,181.1 119.8,166.012 117.941,164.153 U4.11
I2S-WS: U4.13 U7.14 | length 31.1
  Top Layer w0.2: U7.14@113.252,180.6 113.252,181.248 113.547,181.544 118.502,181.544 119.196,180.85 119.196,166.263 115.401,162.468 U4.13
IO0: Q5.6 U4.25 | length 55.8
  Top Layer w0.2: v1(114.1,139.5) 114.1,141.284 U4.25 ; v1(133.5,106.5) 135.36,106.5 Q5.6
  Bottom Layer w0.2: v1(114.1,139.5) 113.704,139.104 113.704,121.996 113.904,121.796 113.904,117.496 114.4,117 114.4,107.408 115.308,106.5 v1(133.5,106.5)
IO4: CARD1.2 U4.26 | length 32.2
  Top Layer w0.2: U4.26 115.401,146.101 116,146.7 116,152.9 118.102,155.002 123.502,155.002 123.7,155.2 v1(123.7,155.5) ; v1(123.7,165.6) 123.7,166.85 CARD1.2
  Bottom Layer w0.2: v1(123.7,155.5) v1(123.7,165.6)
IO12: Q8.1 R45.2 U4.14 | length 7.3
  Top Layer w0.2: Q8.1 112.247,163.903 R45.2 112.2,162.353 112.2,161.6 112.6,161.2 113.731,161.2 114.131,160.8 U4.14
IO13: R46.2 U4.16 | length 16.8
  Top Layer w0.2: R46.2 110.6,166.3 111.3,165.6 111.3,154.8 111.8,154.3 113.09,154.3 U4.16
IO16: CN1.15 R50.2 U4.27 | length 33.7
  Top Layer w0.2: U4.27 116.686,141.299 116.686,138.514 117.186,138.014 v1(122.464,138.014) 124.959,138.014 125.461,137.512 127.4,137.512 127.859,137.054 R50.2 ; CN1.15 v1(127.235,124.814)
  Bottom Layer w0.2: v1@122.586,138.014 122.683,138.112 123.942,138.112 125.69,136.365 125.69,127.11 127.235,125.565 v1(127.235,124.814)
IO21: R35.2 U3.13 U4.33 U13.1 | length 68.3
  Top Layer w0.2: U4.33 124.291,139.109 125.586,137.814 128.54,137.814 128.542,137.812 142.788,137.812 143.486,137.114 143.486,134.814 142.732,134.061 R35.2 v1(142.586,132.914) 142.6,132.9 142.6,128.3 141.85,127.55 U13.1 ; U3.13 143.5,101.054 143.9,101.454 v1(143.9,103.575)
  Bottom Layer w0.2: v1(142.586,132.914) 143.686,131.814 143.686,111.387 143.9,111.173 v1(143.9,103.575)
IO22: R34.2 U3.2 U4.36 U13.4 | length 79.4
  Top Layer w0.2: U4.36 128.101,138.899 128.886,138.114 142.923,138.114 143.802,137.236 143.802,134.23 v1(143.586,134.014) ; U3.2 134.1,101.054 133.6,101.554 133.6,103.1 135.1,104.6 v1(142.765,104.6) ; U13.4 140.35,127.25 140.7,127.6 141.473,127.6 142.298,128.425 142.298,132.1 ; R34.2@141,134.047 141.032,134.014 v1(141.386,134.014) 141.386,133.014 142.298,132.102
  Bottom Layer w0.2: v1(142.765,104.6) 143.2,104.6 143.598,104.998 ; v1(143.586,134.014) v1(141.386,134.014) 141.386,132.914 142,132.3 142.773,132.3 143.384,131.689 143.384,111.262 143.598,111.048 143.598,105
IO25: Q3.1 Q9.1 R27.1 R39.1 R57.1 U4.10 | length 148.6
  Top Layer w0.2: v1(113.8,116.5) 114,116.3 114,114.847 R39.1 116.347,112.5 117.761,112.5 118.963,113.702 139.7,113.702 140.847,114.849 R57.1 140.847,117.103 Q9.1 ; U4.10 119.211,164.996 120.102,165.887 120.102,175.602 120.6,176.1 v1(135.7,176.1) 135.747,176.147 R27.1 135.55,176.897 Q3.1
  Bottom Layer w0.2: v1(113.8,116.5) 113.8,117.1 113.5,117.4 113.5,119.615 113.6,119.715 113.6,121.6 113.402,121.798 113.402,148.975 117.025,152.598 126.398,152.598 127.9,154.1 127.9,156.2 127.7,156.4 127.7,175.4 128.1,175.8 135.4,175.8 v1(135.7,176.1)
IO32: U4.8
IO33: U4.9
IO34: pad.1@136.2,144.9 R52.1 U4.6 | length 26.8
  Top Layer w0.2: U4.6 124.291,156.409 124.686,156.014 133.586,156.014 134.2,155.4 134.2,145.5 134.8,144.9 136.2,144.9 136.653,144.447 R52.1
IO35: pad.1@136.2,164.1 R54.1 U4.7 | length 26.4
  Top Layer w0.2: U4.7 123.021,156.882 124.202,155.7 133.1,155.7 133.4,155.4 v1(133.5,155.4) ; v1(135.1,164.1) 136.2,164.1 136.753,163.547 R54.1
  Bottom Layer w0.2: v1(133.5,155.4) 134.4,155.4 134.7,155.7 134.7,163.9 134.9,164.1 v1(135.1,164.1)
IO39: pad.1@136.2,154.5 R53.1 U4.5 | length 16.2
  Top Layer w0.2: U4.5 125.561,156.739 125.984,156.316 133.711,156.316 134.502,155.525 134.502,154.8 134.802,154.5 136.2,154.5 136.753,153.947 R53.1
OUTN: pad.1@94.5,172.2 U11.2 | length 12.1
  Top Layer w0.2: pad.1@94.714,172.187 94.727,172.2 106.4,172.2 U11.2
OUTP: pad.1@94.6,180.6 U12.2 | length 12.2
  Top Layer w0.2: pad.1@94.6,180.6 94.8,180.8 U12.2
PREVGH: C6.2 CN1.4 D3.1 | length 12.1
  Top Layer w0.2: CN1.4 121.736,125.764 121.486,126.014 121.486,128.514 C6.2 120.686,129.514 120.686,133.214 121.086,133.614 D3.1
PREVGL: C8.2 CN1.2 D2.2 | length 13
  Top Layer w0.2: D2.2 116.386,133.614 117.1,132.9 117.1,129.5 C8.2 117.986,127.714 118.586,127.114 119.286,127.114 120.736,125.664 CN1.2
RESE: CN1.22 Q1.2 R2.2 | length 14
  Top Layer w0.2: CN1.22 130.736,125.564 132.286,127.114 R2.2 131.486,129.261 131.486,132.414 130.5,133.4 130.5,135.264 130.8,135.564 Q1.2
RTS: Q5.2 Q5.4 U5.6 | length 7.2
  Top Layer w0.2: U5.6 132.799,109.837 132.799,108.161 133.249,107.711 135.249,107.711 Q5.4@135.349,107.811 ; Q5.2 136.6,107.1 135.95,107.75 Q5.4@135.628,107.75 ; Q5.4@135.349,107.811 Q5.4 Q5.4@135.628,107.75 ; Q5.4@135.349,107.811 135.567,107.811 Q5.4@135.628,107.75
RXD: U4.34 U5.8 | length 60.6
  Top Layer w0.2: v1(125.5,143.4) 125.5,141.375 U4.34 ; v1(130.6,111.7) 130.843,111.457 U5.8
  Bottom Layer w0.2: v1(125.5,143.4) 125.5,143.6 125.202,143.898 116.625,143.898 115.502,142.775 115.502,139.069 114.708,138.275 114.708,122.446 114.908,122.246 114.908,117.946 115.404,117.45 115.404,113.623 115.827,113.2 129.1,113.2 v1(130.6,111.7)
SOUND-DB: R44.1 R46.1 | length 1.6
  Top Layer w0.2: R46.1 R44.1
SUND-3V3: C33.2 C34.2 R56.1 U7.7 U7.8 U8.2 | length 11
  Top Layer w0.2: U8.2 112.05,170.8 112.25,171 112.598,171 113.1,171.502 113.1,171.956 113.244,172.1 C33.2 C34.2 113.7,177.048 U7.8 U7.7 113.252,175.849 113.003,175.6 R56.1
SUND-GND: Q8.3 U7.3 U7.11 U7.15 | length 34.8
  Top Layer w0.2: v1(110.7,177.2) 110.302,177.598 110.302,178.25 110.6,178.548 U7.3 ; v1(111.1,180.8) 111.1,181.245 111.399,181.544 112.6,181.544 112.752,181.392 U7.15 ; Q8.3 114.8,166.1 115.957,167.257 115.957,175.807 116.293,176.144 116.293,178.829 ; U7.11 116.073,179.05 116.293,178.829 ; v1(116.4,179.6) 116.293,179.494 116.293,178.829
  Bottom Layer w0.2: v1(110.7,177.2) 111,177.2 111.1,177.3 v1(111.1,180.8) 111.1,180.898 111.6,181.398 116.475,181.398 116.696,181.177 116.696,180.2 116.4,179.904 v1(116.4,179.6)
SWITCHIN: SW1.2 U2.3 U8.3 | length 90.9
  Top Layer w0.3: v2(112.1,167.5) 112.1,167.765 112.293,167.958 112.807,167.958 U8.3 ; U2.3 117.135,110.26
  Top Layer w0.5: v2(113,111.3) 116.095,111.3 117.1,110.295 117.1,111.2 119.15,113.25 137.637,113.25 139.437,111.45 139.437,110.4 139.887,109.95 SW1.2@140.675,109.95
  Bottom Layer w0.3: v2(112.1,167.5) 112.2,167.4 112.2,111.6 112.5,111.3 v2(113,111.3)
SWITCHOUT: C22.2 D4.1 Q2.2 SW1.3 | length 32
  Top Layer w0.5: Q2.2 117.7,106.85 D4.1 118.55,109.1 119.364,109.914 C22.2 ; C22.2@119.4,109.929 119.4,112.1 119.848,112.548 136.652,112.548 138.6,110.6 138.6,107.8 139.5,106.9 140.625,106.9 SW1.3@140.675,106.95
TXD: U4.35 U5.9 | length 61.9
  Top Layer w0.2: v1(126.8,143.3) 126.8,141.345 U4.35 ; v1(129.5,111.7) 129.525,111.7 129.843,111.382 U5.9
  Bottom Layer w0.2: v1(126.8,143.3) 126.8,143.7 126.3,144.2 116.5,144.2 115.2,142.9 115.2,139.194 114.406,138.4 114.406,122.321 114.606,122.121 114.606,117.821 115.102,117.325 115.102,113.498 115.8,112.8 128.4,112.8 v1(129.5,111.7)
VBAT: C13.1 C23.2 C24.2 P1.2 Q2.3 Q7.2 R40.1 U1.3 U3.6 | length 71.6
  Top Layer w0.2: Q7.2 110.6,118.65 110.6,114.547 111.2,113.947 R40.1 v1(111.5,112.9) ; 114.15,103.565 114.885,104.3 v1(115.6,104.3) ; v1(121.686,101.814) 124.486,101.814 125.186,101.114 126.286,101.114 128.086,101.114 128.786,101.814 131.986,101.814 133.386,100.414 133.386,96.574 133.986,95.974 U3.6
  Top Layer w0.5: C13.1 114,101.7 114.15,101.85 U1.3 114.15,103.565 114.15,105.785 114.265,105.9 Q2.3
  Top Layer w0.6: P1.2@111.65,92.3 111.65,98.25 112.3,98.9 112.3,101.6 C13.1
  Bottom Layer w0.2: v1(111.5,112.9) 111.5,94.609 111.65,94.459 P1.2 ; v1(115.6,104.3) 116.7,104.3 119.186,101.814 v1(121.686,101.814)
VBUS: D4.2 Q2.1 Q4.1 R5.1 R28.2 R31.2 U9.A4 U9.A9 U9.B4 U9.B9 | length 35.2
  Top Layer w0.3: U9.A4@124.25,95.757 124.25,97.521 123.671,98.1 123.671,98.3 128.6,98.3 129.35,97.55 U9.A9@129.35,95.757
  Top Layer w0.5: Q2.1 118.897,104.95 ; R5.1 120.6,96.6 122.3,98.3 ; 123.671,98.3 122.4,98.3 120.686,100.014 120.686,103.614 119.35,104.95 118.897,104.95 ; R28.2@125.332,105.714 125.332,107.349 Q4.1 124.982,107.7 D4.2 120.932,107.7 120.047,106.814 120.047,106.1 118.897,104.95
VCC-R: C12.1 R3.1 R5.2 U1.4 | length 8.6
  Top Layer w0.5: U1.4 114.15,100.414 114.75,101.014 116.832,101.014 117.847,100 R3.1 118.047,98.353 C12.1 118.1,96.653 R5.2
"": CARD1.1 CARD1.8 CARD1.9 CARD1.10 CARD1.11 CARD1.12 CARD1.13 CN1.18 CN1.19 CN1.21 CN1.24 CN1.25 CN1.26 SW1.1 SW1.4 SW2.3 SW2.4 U3.1 U3.3 U3.4 U3.5 U3.8 U3.9 U3.12 U3.14 U4.17 U4.18 U4.19 U4.20 U4.21 U4.22 U4.32 U5.5 U5.11 U7.5 U7.6 U7.12 U7.13 U7.17 U9.A8 U9.B8 U13.3 U13.6 U13.9

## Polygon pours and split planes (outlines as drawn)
GND on Top Layer (solid, remove dead copper, pour order 0): 79.8,81.9 153,81.9 153,192.9 79.8,192.9
GND on Bottom Layer (solid, remove dead copper, pour order 1): 76.2,76.2 155.6,76.2 155.6,197.5 76.2,197.5

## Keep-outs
Board Outline Layer:
  lines w0.2 net "": 109.3,170.5 109.329,170.471 109.329,168.4 109.329,92.8 109.329,90.8 ccw(c110.803,90.876) 110.8,89.4 ; 109.329,170.5 90.931,170.5 90.931,182.4 142.3,182.4 cw(c142.125,180.625) 143.9,180.8 143.9,174.4 137.786,174.4 137.786,140.414 144.3,140.414 144.3,90.899 ; 110.803,89.4 116.2,89.4 142.9,89.4 ccw(c142.798,90.899) 144.3,90.9

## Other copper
Top Layer:
  drawing of 371 lines, arcs and shapes, not listed
Bottom Layer:
  region net VBAT: 111.55,93.589 111.3,93.133 112,93.133 111.75,93.589
  region net $1N5042: 125.7,97.132 125.65,97.34 125.45,97.34 125.4,97.132
  region net $1N5135: 128.736,97.347 128.686,97.554 128.486,97.554 128.436,97.347
  region net $1N5042: 125.7,97.132 125.65,97.34 125.45,97.34 125.4,97.132
  region net VBAT: 121.553,101.964 121.346,101.914 121.346,101.714 121.553,101.664
  region net VBAT: 115.732,104.15 115.94,104.2 115.94,104.4 115.732,104.45
  region net $1N5042: 122.636,99.982 122.784,99.774 123.067,99.774 122.936,99.982
  region net 3V3: 132.036,111.247 132.156,111.444 131.884,111.454 131.736,111.247
  region net DATA+: 126.7,96.947 126.65,97.154 126.45,97.154 126.4,96.947
  region net DATA+: 127.7,96.947 127.65,97.15 127.45,97.15 127.4,96.947
  region net $1N5135: 130.636,100.182 130.504,99.974 130.787,99.974 130.936,100.182
  region net $1N5135: 130.636,100.182 130.504,99.974 130.787,99.974 130.936,100.182
  region net $1N5135: 130.636,100.182 130.686,100.114 130.886,100.114 130.936,100.182
  region net DATA-: 127.936,97.583 128.125,97.74 128.093,97.99 127.897,97.88
  region net DATA-: 129.25,102.768 129.3,102.56 129.5,102.56 129.55,102.768
  region net DATA+: 128.636,103.182 128.686,102.974 128.886,102.974 128.936,103.182
  region net DIN: 129.236,139.682 129.286,139.474 129.486,139.474 129.536,139.682
  region net CS: 126.385,124.947 126.335,125.114 126.135,125.114 126.085,124.947
  region net CLK: 125.748,126.114 125.566,126.226 125.424,126.084 125.536,125.902
  region net IO16: 127.385,124.947 127.335,125.154 127.135,125.154 127.085,124.947
  region net BUSY: 127.936,125.347 127.886,125.497 127.686,125.497 127.636,125.347
  region net DC: 128.568,125.832 128.718,126.005 128.63,126.2 128.445,126.106
  region net DIN: 129.436,127.247 129.386,127.454 129.186,127.454 129.136,127.247
  region net CLK: 120.336,139.382 120.386,139.174 120.586,139.174 120.636,139.382
  region net CS: 119.046,139.682 119.096,139.474 119.296,139.474 119.346,139.682
  region net DC: 121.773,139.415 121.955,139.303 122.097,139.445 121.985,139.627
  region net IO22: 143.453,134.164 143.246,134.114 143.246,133.914 143.453,133.864
  region net IO22: 141.236,133.882 141.286,133.674 141.486,133.674 141.536,133.882
  region net IO22: 141.518,133.864 141.726,133.914 141.726,134.114 141.518,134.164
  region net VBAT: 111.35,112.768 111.4,112.56 111.6,112.56 111.65,112.768
  region net ADC-BAT: 113.25,114.532 113.2,114.74 113,114.74 112.95,114.532
  region net ADC-BAT: 112.95,120.468 113,120.26 113.2,120.26 113.25,120.468
  region net ADC-BAT: 113.25,120.732 113.2,120.94 113,120.94 112.95,120.732
  region net IO25: 113.95,116.632 113.9,116.84 113.7,116.84 113.65,116.632
  region net IO0: 133.368,106.65 133.16,106.6 133.16,106.4 133.368,106.35
  region net IO0: 113.9,139.513 113.789,139.33 113.93,139.189 114.113,139.3
  region net TXD: 129.513,111.9 129.33,112.011 129.189,111.87 129.3,111.688
  region net RXD: 130.613,111.9 130.43,112.011 130.289,111.87 130.4,111.688
  region net EN: 134.068,108.85 133.86,108.8 133.86,108.6 134.068,108.55
  region net RXD: 125.65,143.532 125.501,143.74 125.219,143.74 125.35,143.532
  region net TXD: 126.95,143.432 126.9,143.64 126.7,143.64 126.65,143.432
  region net EN: 128.187,156.6 128.37,156.489 128.511,156.63 128.4,156.813
  region net EN: 128.35,156.932 128.3,157.14 128.1,157.14 128.05,156.932
  region net ADC-BAT: 126.65,156.668 126.7,156.46 126.9,156.46 126.95,156.668
  region net DC: 129.35,155.132 129.3,155.34 129.1,155.34 129.05,155.132
  region net DC: 129.05,165.468 129.1,165.26 129.3,165.26 129.35,165.468
  region net CLK: 127.496,155.142 127.498,155.379 127.298,155.491 127.234,155.289
  region net IO4: 123.85,155.632 123.8,155.84 123.6,155.84 123.55,155.632
  region net IO4: 123.55,165.468 123.6,165.26 123.8,165.26 123.85,165.468
  region net IO25: 135.5,176.113 135.389,175.93 135.53,175.789 135.713,175.9
  region net 3V3: 135.532,147.25 135.606,147.3 135.606,147.5 135.532,147.55
  region net SWITCHIN: 112.802,111.525 112.5,111.45 112.5,111.15 112.802,111.075
  region net SWITCHIN: 111.954,167.238 112.05,166.941 112.35,167.048 112.378,167.388
  region net $2N1555: 115.932,178.35 116.14,178.4 116.14,178.6 115.932,178.65
  region net SUND-GND: 116.55,179.732 116.5,179.904 116.3,179.904 116.25,179.732
  region net 3V3: 136.568,91.55 136.36,91.5 136.36,91.3 136.568,91.25
  region net IO22: 142.897,104.45 143.105,104.5 143.105,104.7 142.897,104.75
  region net IO21: 144.05,103.707 144,103.915 143.8,103.915 143.75,103.707
  region net IO21: 142.573,132.715 142.755,132.603 142.897,132.745 142.785,132.927
  region net IO35: 133.632,155.25 133.84,155.3 133.84,155.5 133.632,155.55
  region net EN: 139.45,178.968 139.5,178.76 139.7,178.76 139.75,178.968
  region net 3V3: 135.568,116.05 135.36,116 135.36,115.8 135.568,115.75
  region net DC: 126.55,122.168 126.6,121.96 126.8,121.96 126.85,122.168
  region net CS-OUT: 114.732,143.949 114.94,143.999 114.94,144.199 114.732,144.249
  region net CS-OUT: 138.55,127.532 138.5,127.74 138.3,127.74 138.25,127.532
  region net CLK: 127.05,162.968 127.1,162.76 127.3,162.76 127.35,162.968
  region net DIN: 125.65,160.968 125.7,160.76 125.9,160.76 125.95,160.968
  region net DIN: 126.013,153.8 125.871,153.871 125.729,153.729 125.8,153.588
  region net 3V3: 136.321,128.355 136.533,128.4 136.547,128.6 136.343,128.655
  region net 3V3: 137.668,128.65 137.46,128.6 137.46,128.4 137.668,128.35
  region net IO35: 134.968,164.25 134.76,164.101 134.771,163.829 134.968,163.95
  region net $1N1499: 117.65,101.468 117.7,101.26 117.9,101.26 117.95,101.468
  region net $1N1499: 117.95,92.032 117.9,92.24 117.7,92.24 117.65,92.032
  region net $2N1588: 115.632,177.35 115.84,177.4 115.84,177.6 115.632,177.65
  region net SUND-GND: 110.95,180.668 111,180.46 111.2,180.46 111.25,180.668
  region net SUND-GND: 111.292,180.857 111.386,181.042 111.193,181.132 111.019,180.983
  region net SUND-GND: 110.832,177.05 111,177.1 111,177.3 110.832,177.35
  region net $2N1555: 109.3,172.588 109.411,172.77 109.27,172.911 109.087,172.8
  region net $2N1588: 109.3,181.488 109.411,181.67 109.27,181.811 109.087,181.7
  region net 8025INT: 134,114.713 133.889,114.53 134.03,114.389 134.213,114.5
  region net 8025INT: 139.85,92.132 139.701,92.34 139.419,92.34 139.55,92.132
  region net 8025INT: 135.988,114.5 136.129,114.429 136.271,114.571 136.2,114.713
  region net 8025INT: 115.25,125.168 115.3,124.96 115.5,124.96 115.55,125.168
  region net DC: 138.75,126.468 138.8,126.26 139,126.26 139.05,126.468
  region net $4N231: 140.95,126.868 141,126.66 141.2,126.66 141.25,126.868
  region net $4N231: 140.95,126.868 141,126.66 141.2,126.66 141.25,126.868
  region net $4N231: 141.613,121 141.43,121.111 141.289,120.97 141.4,120.788

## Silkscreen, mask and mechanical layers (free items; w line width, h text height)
Top Silkscreen Layer:
  text "68UH" at 102.799,180.466 h0.78
  text "MAX98357" at 103.363,178.466 h0.78
  text "10K" at 139.266,176.897 h0.78 r270
  text "SPEAKER" at 92.197,176.066 h0.78
  text "0R" at 108.268,175.166 h0.78
  text "10u" at 114.572,173.666 h0.78
  text "200K" at 106.499,173.466 h0.78
  text "CJ2302" at 133.031,173.066 h0.78
  text "68UH" at 102.844,172.166 h0.78
  text "1u" at 114.712,171.772 h0.78
  text "10K" at 134.234,171.666 h0.78
  text "6206" at 111.499,168.566 h0.78
  text "0R" at 110.166,168.432 h0.78 r270
  text "0.1u" at 132.038,165.966 h0.78
  text "2302" at 109.399,164.766 h0.78
  text "I35" at 132.676,163.666 h0.78
  text "10K" at 117.134,163.366 h0.78
  text "22u" at 119.334,163.366 h0.78
  text "10K" at 114.934,163.266 h0.78
  text "10K" at 109.534,162.066 h0.78
  text "0.1u" at 114.838,161.666 h0.78
  text "10K" at 117.21,161.666 h0.78
  text "0.1u" at 119.299,161.666 h0.78
  text "10K" at 132.41,161.266 h0.78
  text "0.1u" at 132.138,156.466 h0.78
  text "I39" at 132.376,154.166 h0.78
  text "10K" at 132.341,151.666 h0.78
  text "0.1u" at 132.175,146.966 h0.78
  text "I34" at 132.41,144.566 h0.78
  text "10K" at 132.334,142.366 h0.78
  text "0.1u" at 123.352,138.198 h0.78
  text "10K" at 127.525,137.912 h0.78 r270
  text "0530" at 115.63,137.004 h0.78
  text "10uH" at 133.799,136.966 h0.78
  text "0530" at 122.899,136.866 h0.78
  text "2302" at 129.099,136.766 h0.78
  text ".47R" at 131.966,133.401 h0.78 r270
  text "0.1u" at 128.466,133.001 h0.78 r270
  text "0.1u" at 135.166,132.901 h0.78 r270
  text "10K" at 137.666,132.867 h0.78 r270
  text "10K" at 133.566,132.767 h0.78 r270
  text "10K" at 142.252,132.714 h0.78 r270
  text "10K" at 140.666,132.69 h0.78 r270
  text "1u" at 115.866,132.332 h0.78 r270
  text "1u" at 117.666,132.223 h0.78 r270
  text "1u" at 119.366,132.223 h0.78 r270
  text "1u" at 121.266,132.223 h0.78 r270
  text "1u" at 123.066,132.223 h0.78 r270
  text "1u" at 124.858,132.178 h0.78 r270
  text "1u" at 126.666,132.123 h0.78 r270
  text "1u" at 130.255,132.122 h0.78 r270
  text "22u" at 111.112,127.426 h0.78
  text "100K" at 110.799,126.166 h0.78
  text "CJ2301" at 109.331,124.966 h0.78
  text "S8050" at 113.865,124.966 h0.78
  text "GXHT30" at 134.731,123.666 h0.78
  text "CJ2302" at 135.331,117.866 h0.78
  text "1M" at 138.668,114.966 h0.78
  text "10K" at 114.503,113.074 h0.78 r270
  text "1M" at 116.166,113.032 h0.78 r270
  text "100K" at 111.166,113.017 h0.78 r270
  text "100K" at 112.666,113.008 h0.78 r270
  text "CH340K" at 128.731,111.466 h0.78
  text "10u" at 119.034,111.066 h0.78
  text "6206" at 115.551,110.908 h0.78 r270
  text "CJ2302" at 123.831,110.566 h0.78
  text "NPN" at 135.234,108.666 h0.78
  text "3401" at 115.582,107.308 h0.78 r270
  text "22u" at 110.466,105.841 h0.78 r270
  text "22u" at 112.266,105.841 h0.78 r270
  text "RX8025" at 136.331,104.266 h0.78
  text "1MR" at 125.034,103.766 h0.78
  text "4007" at 118.499,103.666 h0.78
  text "1M" at 119.468,102.566 h0.78
  text "10u" at 125.166,100.167 h0.78 r270
  text "0.1u" at 127.266,100.175 h0.78 r270
  text "5.1K" at 130.466,100.175 h0.78 r270
  text "5.1K" at 122.466,100.001 h0.78 r270
  text "10u" at 110.559,99.671 h0.78
  text "TP4055" at 109.931,98.066 h0.78
  text "1.66K" at 115.766,95.859 h0.78 r270
  text "1K" at 118.168,94.866 h0.78
  text "1uF" at 117.834,93.666 h0.78
  text "1R" at 118.068,92.466 h0.78
  text "10K" at 140.434,90.966 h0.78
  text "LED" at 113.91,90.166 h0.78
Bottom Silkscreen Layer:
  text "TF卡： /  CLK:   IO18 /  MISO:  IO19 /  MOSI:  IO23 /  CS:    IO04" at 121.77,169.725 h1.72
  text "Eink： /  CLK:   IO18 /  MISO:  IO19 /  MOSI:  IO23 /  CS:    IO05" at 133.695,169.575 h1.72
  text "按键： /  上:  IO35 /  中:  IO39 /  下:  IO34" at 121.895,156.892 h1.72
  text "其他： /  BAT:   IO36 /  WAKE:  IO25 /  AMP:   IO34 /  RX8025INT:IO15" at 133.12,156.828 h1.72
  text "I2C： /  SCL:  IO22 /  SDA:  IO21" at 133.195,146.766 h1.72
  text "I2S： /  SDA:  IO26 /  SCK:  IO27 /  WS:   IO14 /  WAKE: IO32 /  S-DB: IO13" at 121.745,144.503 h1.72
Mechanical Layer:
  lines w0.025 net "": 117.986,115.6 117.986,117.2 ccw(c120.986,117.2) 120.986,114.2 130.986,114.2 ccw(c130.986,117.2) 133.986,117.2 133.986,115.6 ccw(c130.986,115.6) 130.986,118.6 120.986,118.6 ccw(c120.986,115.6) 117.986,115.6 ; 136,93.2 141.6,93.2 141.6,103.8 136,103.8 136,93.2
